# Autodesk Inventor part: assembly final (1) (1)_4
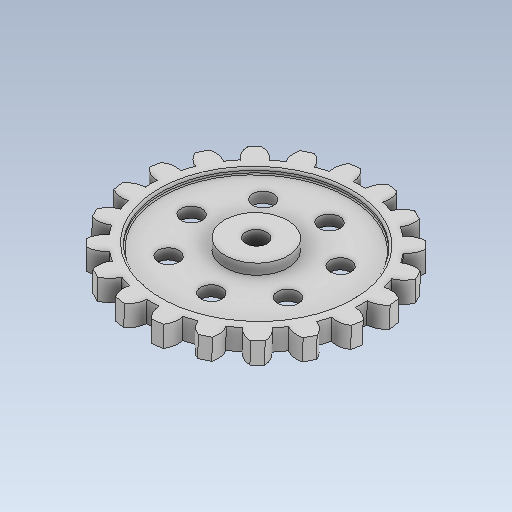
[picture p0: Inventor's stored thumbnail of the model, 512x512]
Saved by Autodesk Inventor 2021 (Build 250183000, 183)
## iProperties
Created: 2021-07
Part Number: assembly final (1) (1)_4
Material: Generic
Document SubType Name: Modeling
Designer: TARUN
Density: 1 g/cm^3
Appearance: Default
Author: TARUN
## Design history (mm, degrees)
feature "Base1"
body "Solid1"
